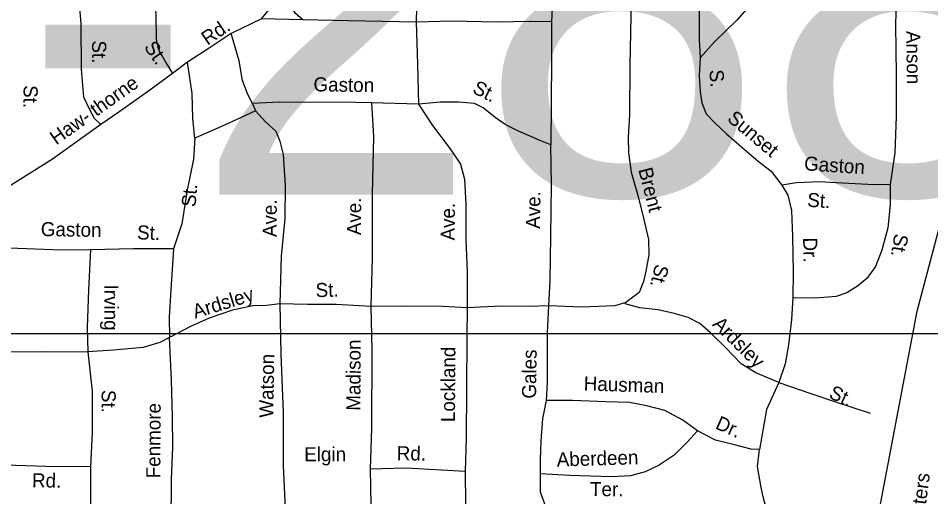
# Model space of a CAD drawing. Extents: x 1551653 to 1702041, y 811336 to 920032.
# Drawn here: x 1623759 to 1628010, y 849457 to 851687 of the extents above; entities that cross this region are included whole.
import ezdxf

# ---------------------------------------------------------------- set-up
doc = ezdxf.new("R2010")
doc.units = 0
for name, color, linetype in [('Old_Level_10', 7, 'Continuous'), ('Old_Level_3', 7, 'Continuous'), ('Old_Level_35', 7, 'Continuous'), ('Old_Level_59', 7, 'Continuous')]:
    doc.layers.add(name, color=color, linetype=linetype)

msp = doc.modelspace()

# ---------------------------------------------------------------- linework, layer by layer
at = {"layer": 'Old_Level_3'}
msp.add_lwpolyline([(1628212.746, 850215.277), (1622518.859, 850215.277), (1621376.229, 850215.277), (1621376.229, 851475.417), (1621376.229, 851926.742), (1621376.229, 853133.878), (1626214.433, 853133.878), (1628212.746, 853133.878), (1628212.746, 852848.761), (1628212.746, 850215.277)], dxfattribs=at)
at = {"layer": 'Old_Level_35'}
for p, q in [((1624892.804, 851684.252), (1625014.874, 851832.46)), ((1624892.804, 851684.252), (1624750.389, 851616.01)), ((1625084.411, 851679.564), (1624892.804, 851684.252)), ((1624548.006, 851481.764), (1624477.514, 851429.431)), ((1624850.767, 851289.085), (1624864.284, 851254.991)), ((1625623.721, 851286.008), (1625404.342, 851292.862))]:
    msp.add_line(p, q, dxfattribs=at)
for points in [[(1624143.695, 851191.884), (1624114.133, 851219.188), (1624091.394, 851262.42), (1624064.106, 851319.303), (1624053.983, 851448.931), (1624053.038, 851658.865), (1624035.107, 851877.436), (1624025.73, 852036.948), (1624019.478, 852183.949)], [(1624393.185, 852209.477), (1624391.151, 852079.645), (1624390.095, 851869.75), (1624399.452, 851699.665), (1624401.824, 851589.754), (1624411.092, 851543.54), (1624447.966, 851477.156), (1624477.514, 851429.431)], [(1626255.068, 852055.836), (1626252.257, 851867.988), (1626243.244, 851670.262)], [(1627847.461, 852049.55), (1627851.207, 851902.184), (1627845.577, 851654.36), (1627847.916, 851424.387), (1627848.943, 851228.456), (1627842.496, 851058.692), (1627820.291, 850911.061)], [(1626618.548, 852040.455), (1626612.672, 851918.507), (1626613.414, 851698.569), (1626607.876, 851464.954), (1626606.252, 851237.058), (1626600.743, 851133.115), (1626601.646, 851059.253), (1626614.224, 850969.148), (1626646.56, 850856.629), (1626674.657, 850742.397), (1626695.32, 850656.131), (1626696.258, 850584.07), (1626683.115, 850508.296), (1626672.341, 850460.488), (1626651.685, 850408.877), (1626589.093, 850361.718)], [(1625612.143, 851977.831), (1625615.457, 851805.866), (1625613.462, 851668.031)], [(1626931.691, 851999.684), (1626929.535, 851863.851), (1626931.133, 851705.932), (1626931.343, 851588.061), (1626935.999, 851501.92)], [(1627228.711, 851963.241), (1627217.451, 851881.624), (1627200.345, 851807.929), (1627173.642, 851754.242), (1627106.448, 851677.362), (1627003.157, 851577.001), (1626935.999, 851501.92)], [(1625084.411, 851679.564), (1625050.979, 851708.458), (1625028.899, 851744.527), (1625021.937, 851776.286), (1625014.874, 851832.46)], [(1625613.462, 851668.031), (1625454.053, 851671.863), (1625298.216, 851674.226), (1625084.411, 851679.564)], [(1626243.244, 851670.262), (1626147.417, 851671.604), (1625985.459, 851668.087), (1625779.652, 851673.064), (1625613.462, 851668.031)], [(1625613.462, 851668.031), (1625618.488, 851472.018), (1625623.721, 851286.008)], [(1626243.244, 851670.262), (1626242.598, 851500.381), (1626241.42, 851284.482), (1626240.61, 851096.596)], [(1624750.389, 851616.01), (1624648.061, 851547.75), (1624548.006, 851481.764)], [(1624850.767, 851289.085), (1624829.418, 851331.543), (1624804.31, 851395.886), (1624787.768, 851488.074), (1624750.389, 851616.01)], [(1626935.999, 851501.92), (1626930.739, 851420.181), (1626935.598, 851344.039), (1626942.747, 851292.068), (1626964.142, 851241.805), (1627003.298, 851199.187), (1627058.498, 851148.439), (1627129.456, 851085.365), (1627206.375, 851020.169), (1627265.657, 850973.341), (1627316.575, 850908.673)], [(1624582.542, 851127.232), (1624572.004, 851219.299), (1624569.757, 851335.407), (1624548.006, 851481.764)], [(1624477.514, 851429.431), (1624372.912, 851352.069), (1624227.832, 851248.767), (1624143.695, 851191.884)], [(1625404.342, 851292.862), (1625258.505, 851295.02), (1625094.588, 851293.544), (1624976.764, 851295.332), (1624850.767, 851289.085)], [(1625404.342, 851292.862), (1625413.941, 851134.778), (1625407.668, 850865.156), (1625407.314, 850571.4), (1625401.891, 850343.582)], [(1626240.61, 851096.596), (1626192.765, 851115.375), (1626089.629, 851160.693), (1626027.621, 851191.566), (1625980.653, 851223.938), (1625924.737, 851269.095), (1625883.734, 851289.738), (1625810.22, 851295.834), (1625726.562, 851295.329), (1625623.721, 851286.008)], [(1625623.721, 851286.008), (1625688.15, 851187.248), (1625770.378, 851077.921), (1625819.173, 851007.291), (1625838.16, 850937.068), (1625844.37, 850819.076), (1625843.845, 850655.196), (1625849.606, 850505.196), (1625851.004, 850337.273)], [(1624864.284, 851254.991), (1624793.778, 851222.002), (1624705.308, 851181.376), (1624582.542, 851127.232)], [(1624864.284, 851254.991), (1624911.485, 851204.407), (1624958.601, 851159.627), (1624977.873, 851113.41), (1624993.023, 851051.268), (1625002.705, 850907.19), (1625000.386, 850753.351), (1624984.154, 850578.221), (1624977.332, 850355.236)], [(1624143.695, 851191.884), (1623918.573, 851030.333), (1623713.347, 850901.206)], [(1624582.542, 851127.232), (1624574.957, 851029.532), (1624545.733, 850885.394), (1624520.719, 850728.394), (1624482.062, 850612.351)], [(1626231.207, 850347.168), (1626236.997, 850464.917), (1626239.973, 850670.77), (1626243.638, 850910.631), (1626240.61, 851096.596)], [(1627820.291, 850911.061), (1627746.233, 850910.162), (1627568.517, 850918.971), (1627490.778, 850923.948), (1627384.833, 850919.696), (1627316.575, 850908.673)], [(1627316.575, 850908.673), (1627343.849, 850862.295), (1627360.794, 850790.11), (1627364.964, 850670.159), (1627368.399, 850504.198), (1627366.565, 850384.169)], [(1627820.291, 850911.061), (1627820.79, 850817.196), (1627809.196, 850709.372), (1627781.683, 850605.875), (1627752.536, 850530.422), (1627711.752, 850473.017), (1627669.212, 850437.66), (1627618.753, 850406.466), (1627568.576, 850389.274), (1627472.589, 850382.617), (1627366.565, 850384.169)], [(1624095.488, 850607.801), (1623961.324, 850605.525), (1623716.758, 850614.512)], [(1624095.488, 850607.801), (1624086.391, 850421.221), (1624079.57, 850246.019), (1624084.118, 850132.252)], [(1624482.062, 850612.351), (1624416.117, 850612.351), (1624295.596, 850612.351), (1624095.488, 850607.801)], [(1624482.062, 850612.351), (1624470.692, 850421.221), (1624461.596, 850293.802), (1624463.87, 850198.237)], [(1624977.332, 850355.236), (1624915.935, 850348.411), (1624852.263, 850346.134), (1624757.212, 850325.656), (1624648.061, 850289.251), (1624561.65, 850250.57), (1624463.87, 850198.237)], [(1624977.332, 850355.236), (1624981.88, 850120.875), (1624992.663, 849850.007), (1624992.994, 849600.06), (1625001.823, 849403.971), (1624998.968, 849204.119), (1624998.611, 849058.247), (1625004.211, 848900.245)], [(1625401.891, 850343.582), (1625240.657, 850352.961), (1625106.948, 850352.961), (1624977.332, 850355.236)], [(1626231.207, 850347.168), (1626139.064, 850342.634), (1626007.024, 850344.113), (1625851.004, 850337.273)], [(1626220.446, 849905.541), (1626223.749, 849989.521), (1626225.216, 850091.348), (1626225.255, 850221.42), (1626231.207, 850347.168)], [(1626589.093, 850361.718), (1626538.759, 850346.531), (1626384.96, 850340.849), (1626231.207, 850347.168)], [(1627302.701, 849989.806), (1627261.015, 850006.459), (1627195.126, 850033.921), (1627126.118, 850076.423), (1627055.34, 850150.803), (1626984.434, 850220.026), (1626933.312, 850264.688), (1626879.627, 850291.591), (1626813.975, 850310.531), (1626740.284, 850327.634), (1626654.624, 850336.778), (1626586.97, 850355.76), (1626589.093, 850361.718)], [(1627366.565, 850384.169), (1627361.099, 850282.421), (1627347.299, 850164.971), (1627331.373, 850076.423), (1627302.701, 849989.806)], [(1625401.891, 850343.582), (1625406.756, 850139.57), (1625405.178, 849775.801), (1625398.328, 849586.034)], [(1625851.004, 850337.273), (1625737.451, 850342.578), (1625569.61, 850344.983), (1625401.891, 850343.582)], [(1625851.004, 850337.273), (1625849.006, 850199.435), (1625847.382, 849961.539), (1625845.883, 849729.84), (1625841.516, 849573.839)], [(1624463.87, 850198.237), (1624418.39, 850175.484), (1624341.076, 850152.73), (1624202.364, 850139.078), (1624084.118, 850132.252)], [(1624484.521, 848879.969), (1624475.623, 848964.198), (1624476.473, 849144.08), (1624471.243, 849330.09), (1624472.454, 849537.78), (1624478.697, 849687.737), (1624476.975, 849829.653), (1624473.418, 849999.619), (1624463.87, 850198.237)], [(1624084.118, 850132.252), (1623999.981, 850129.976), (1623872.639, 850132.252), (1623679.352, 850129.976)], [(1624084.118, 850132.252), (1624102.996, 849949.101), (1624104.105, 849757.172), (1624095.62, 849595.454)], [(1627302.701, 849989.806), (1627244.671, 849863.909), (1627212.397, 849676.829)], [(1627302.701, 849989.806), (1627451.696, 849938.289), (1627561.402, 849901.099), (1627727.729, 849846.199)], [(1626191.308, 849564.141), (1626192.247, 849630.161), (1626195.593, 849716.139), (1626203.1, 849819.846), (1626220.446, 849905.541)], [(1626923.535, 849763.206), (1626854.335, 849814.236), (1626771.206, 849859.347), (1626687.59, 849880.656), (1626605.858, 849895.922), (1626496.072, 849899.551), (1626340.314, 849905.712), (1626220.446, 849905.541)], [(1626923.535, 849763.206), (1626876.871, 849711.923), (1626814.001, 849650.965), (1626745.412, 849603.928), (1626678.945, 849572.858), (1626610.727, 849554.033), (1626524.782, 849549.171), (1626327.02, 849556.185), (1626191.308, 849564.141)], [(1627206.397, 849676.95), (1627173.881, 849678.663), (1627088.948, 849699.914), (1627006.904, 849719.892), (1626923.535, 849763.206)], [(1627247.944, 849385.927), (1627228.965, 849456.354), (1627219.887, 849499.797), (1627202.192, 849597.199), (1627212.397, 849676.829), (1627206.397, 849676.95)], [(1624095.62, 849595.454), (1623887.97, 849598.465), (1623652.001, 849606.266)], [(1624095.62, 849595.454), (1624095.424, 849447.577), (1624092.126, 849235.723), (1624087.966, 848951.852), (1624083.37, 848656.18), (1624074.108, 848436.443), (1624063.501, 848268.767), (1624058.363, 848054.951), (1624055.233, 847861.107)], [(1625841.516, 849573.839), (1625730.004, 849581.106), (1625564.285, 849589.469), (1625398.328, 849586.034)], [(1625398.328, 849586.034), (1625401.763, 849420.073), (1625399.85, 849286.235), (1625404.588, 849214.099), (1625411.451, 849138.118), (1625447.793, 849025.72), (1625467.842, 848899.441)], [(1625841.516, 849573.839), (1625843.278, 849423.922), (1625840.066, 849216.271), (1625841.335, 849032.341), (1625841.06, 848890.468)], [(1626704.037, 847939.443), (1626701.547, 848043.55), (1626693.253, 848147.576), (1626686.147, 848211.555), (1626655.481, 848288.022), (1626612.492, 848358.73), (1626533.893, 848449.777), (1626475.301, 848530.61), (1626450.071, 848588.953), (1626438.923, 848641.007), (1626439.654, 848687.017), (1626401.426, 849061.403), (1626384.399, 849129.585), (1626310.209, 849240.553), (1626245.905, 849345.513), (1626220.751, 849397.852), (1626191.968, 849478.282), (1626191.308, 849564.141)]]:
    msp.add_lwpolyline(points, dxfattribs=at)
at = {"layer": 'Old_Level_59'}
msp.add_lwpolyline([(1627775.821, 849422.976), (1627945.81, 850322.232), (1628138.539, 851048.997), (1628167.778, 851309.096), (1628259.608, 851768.937), (1628324.519, 852110.217), (1628292.063, 852417.725), (1628080.129, 852711.308), (1627545.894, 853515.755), (1627511.371, 853606.275), (1627501.946, 853670.987), (1627519.442, 853773.592), (1627534.003, 853831.388), (1627195.978, 854056.298), (1626798.583, 854418.376)], dxfattribs=at)

# ---------------------------------------------------------------- texts
at = {"layer": 'Old_Level_10'}
for s, height, rotation, p in [('Rd.', 65.6167, 34.127094, (1624640.454, 851558.028)), ('Anson', 65.6167, 270.582778, (1627895.896, 851627.311)), ('St.', 65.6167, 270.257878, (1624103.087, 851583.087)), ('St.', 65.6167, 304.927531, (1624342.734, 851551.914)), ('Haw- thorne', 65.61666, 35.366094, (1623936.089, 851093.933)), ('Gaston', 65.6167, 359.151922, (1625133.863, 851346.098)), ('S.', 65.6167, 273.651333, (1626978.789, 851445.439)), ('St.', 65.6167, 269.367228, (1623784.363, 851375.058)), ('St.', 65.6167, 333.277464, (1625870.312, 851341.431)), ('Sunset', 65.6167, 319.715364, (1627057.354, 851212.167)), ('Gaston', 65.6167, 356.336811, (1627418.314, 850977.969)), ('Brent', 65.6167, 284.272622, (1626647.113, 850981.62)), ('St.', 65.6167, 85.6585, (1624585.144, 850805.208)), ('Ave.', 65.6167, 89.124683, (1626189.342, 850705.101)), ('St.', 65.6167, 356.336811, (1627432.984, 850808.156)), ('Ave.', 65.6167, 89.905931, (1624963.089, 850666.736)), ('Ave.', 65.6167, 89.930889, (1625356.261, 850675.729)), ('Ave.', 65.6167, 89.816475, (1625792.656, 850650.861)), ('Gaston', 65.6167, 359.118483, (1623863.8, 850671.51)), ('St.', 65.6167, 358.366847, (1624312.191, 850656.232)), ('Dr.', 65.6167, 271.185731, (1627414.812, 850664.207)), ('St.', 65.6167, 260.644839, (1627841.085, 850685.461)), ('St.', 65.6167, 255.821072, (1626727.456, 850544.017)), ('Irving', 65.6167, 269.964103, (1624159.951, 850445.484)), ('St.', 65.6167, 1.580286, (1625145.14, 850386.633)), ('Ardsley', 65.6167, 17.190272, (1624583.237, 850286.291)), ('Ardsley', 65.6167, 315.072614, (1626989.106, 850256.931)), ('Madison', 65.6167, 89.751444, (1625352.891, 849857.58)), ('Lockland', 65.6167, 89.608872, (1625793.186, 849804.458)), ('Gales', 65.6167, 89.174875, (1626171.011, 849913.455)), ('Watson', 65.6167, 89.136169, (1624947.233, 849824.512)), ('Hausman', 65.6167, 358.106981, (1626392.338, 849952.257)), ('St.', 65.6167, 334.761931, (1627530.65, 849919.744)), ('St.', 65.6167, 269.916022, (1624147.677, 849954.917)), ('Fenmore', 65.6167, 89.669344, (1624420.781, 849542.431)), ('Dr.', 65.6167, 336.175508, (1627002.016, 849776.134)), ('Elgin', 65.6167, 0.177492, (1625091.338, 849621.907)), ('Rd.', 65.6167, 359.169028, (1625521.659, 849627.049)), ('Aberdeen', 65.6167, 1.623583, (1626268.327, 849597.496)), ('Rd.', 65.6167, 359.169028, (1623822.886, 849500.76)), ('Peters', 65.6167, 82.678547, (1627973.705, 849312.053)), ('Ter.', 65.6167, 359.628906, (1626422.202, 849459.935))]:
    msp.add_text(s, height=height, rotation=rotation, dxfattribs=at).set_placement(p)
at = {"layer": 'Old_Level_3'}
msp.add_text('B-2881', height=1788.0542, dxfattribs=at).set_placement((1622184.436, 850864.085))

doc.saveas('drawing.dxf')
